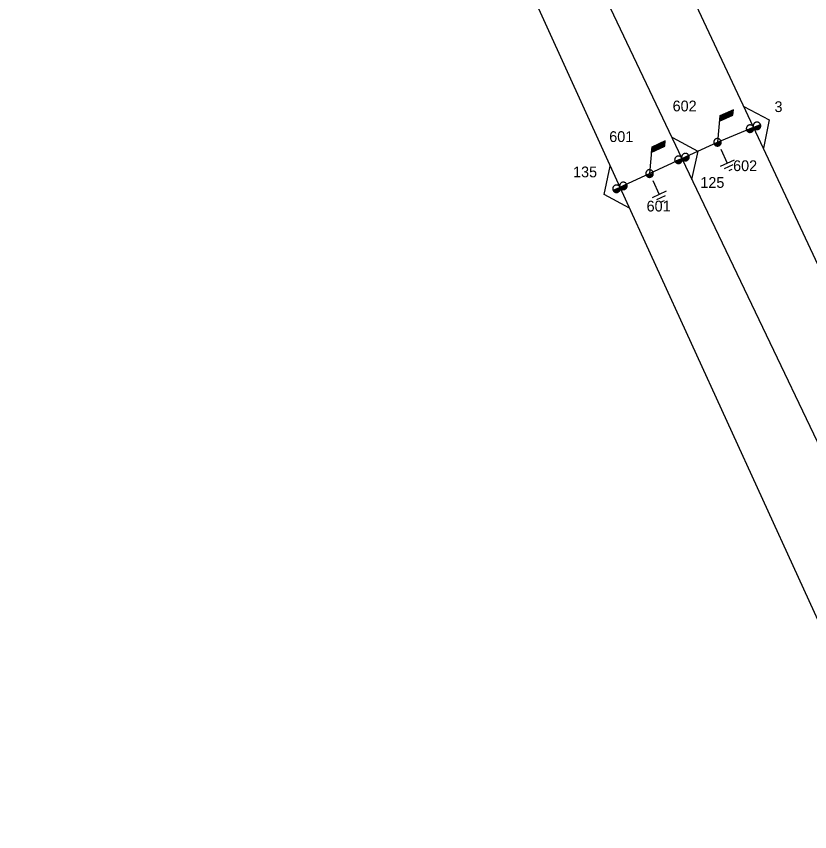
# Model space of a CAD drawing. Extents: x -536397 to -535454, y -1201642 to -1200953.
# Drawn here: x -536387.9 to -536258.8, y -1201274.9 to -1201142.3 of the extents above; entities that cross this region are included whole.
import ezdxf

# ---------------------------------------------------------------- set-up
doc = ezdxf.new("R2010")
doc.units = 0
for name, color, linetype in [('Default', 7, 'Continuous'), ('Vrstva 1', 7, 'Continuous'), ('Vrstva 11', 7, 'Continuous'), ('Vrstva 12', 7, 'Continuous'), ('Vrstva 13', 7, 'Continuous'), ('Vrstva 14', 7, 'Continuous'), ('Vrstva 15', 7, 'Continuous'), ('Vrstva 18', 7, 'Continuous'), ('Vrstva 2', 7, 'Continuous'), ('Vrstva 52', 7, 'Continuous')]:
    doc.layers.add(name, color=color, linetype=linetype)

# ---------------------------------------------------------------- blocks, each defined once
blk = doc.blocks.new('VN860')
at = {"layer": 'Vrstva 15'}
for points in [[(-3.74, 0), (0.01, 2.82)], [(0.01, 2.82), (3.76, 0)]]:
    blk.add_lwpolyline(points, dxfattribs=at)
blk = doc.blocks.new('VN440')
at = {"layer": 'Vrstva 2'}
for points in [[(1.22, 0), (1.21, 0.13), (1.19, 0.25), (1.16, 0.38), (1.11, 0.5), (1.05, 0.61), (0.98, 0.72), (0.9, 0.82), (0.81, 0.91), (0.71, 0.99), (0.6, 1.06), (0.49, 1.12), (0.37, 1.16), (0.25, 1.2), (0.12, 1.22), (-0.01, 1.22), (-0.14, 1.22), (-0.26, 1.2), (-0.39, 1.16), (-0.51, 1.12), (-0.62, 1.06), (-0.73, 0.99), (-0.83, 0.91), (-0.92, 0.82), (-1, 0.72), (-1.07, 0.61), (-1.13, 0.5), (-1.18, 0.38), (-1.21, 0.25), (-1.23, 0.13), (-1.24, 0), (-1.23, -0.13), (-1.21, -0.26), (-1.18, -0.38), (-1.13, -0.5), (-1.07, -0.62), (-1, -0.73), (-0.92, -0.83), (-0.83, -0.92), (-0.73, -1), (-0.62, -1.07), (-0.51, -1.13), (-0.39, -1.17), (-0.26, -1.2), (-0.14, -1.23), (-0.01, -1.23), (0.12, -1.23), (0.25, -1.2), (0.37, -1.17), (0.49, -1.13), (0.6, -1.07), (0.71, -1), (0.81, -0.92), (0.9, -0.83), (0.98, -0.73), (1.05, -0.62), (1.11, -0.5), (1.16, -0.38), (1.19, -0.26), (1.21, -0.13), (1.22, 0)], [(-1.24, 0), (1.22, 0)], [(-1.18, -0.34), (1.1, -0.34)], [(-1.01, -0.63), (0.97, -0.63)], [(-0.74, -0.92), (0.68, -0.92)]]:
    blk.add_lwpolyline(points, dxfattribs=at)
blk = doc.blocks.new('VN810')
at = {"layer": 'Vrstva 14'}
for points in [[(0, -1.25), (0, -3.75)], [(1.25, -3.75), (-1.25, -3.75)], [(0.77, -4.37), (-0.8, -4.37)], [(0, -5), (-0.25, -5)], [(0.27, -5), (0, -5)]]:
    blk.add_lwpolyline(points, dxfattribs=at)
blk = doc.blocks.new('VN450')
at = {"layer": 'Vrstva 2'}
for points in [[(0, 0), (-0.01, 0.13), (-0.03, 0.25), (-0.06, 0.38), (-0.11, 0.5), (-0.16, 0.61), (-0.23, 0.72), (-0.31, 0.82), (-0.4, 0.91), (-0.5, 0.99), (-0.61, 1.06), (-0.72, 1.11), (-0.84, 1.16), (-0.97, 1.19), (-1.09, 1.21), (-1.22, 1.22), (-1.35, 1.21), (-1.47, 1.19), (-1.59, 1.16), (-1.71, 1.11), (-1.83, 1.06), (-1.93, 0.99), (-2.03, 0.91), (-2.12, 0.82), (-2.2, 0.72), (-2.27, 0.61), (-2.33, 0.5), (-2.38, 0.38), (-2.41, 0.25), (-2.43, 0.13), (-2.44, 0), (-2.43, -0.13), (-2.41, -0.25), (-2.38, -0.38), (-2.33, -0.5), (-2.27, -0.61), (-2.2, -0.72), (-2.12, -0.82), (-2.03, -0.91), (-1.93, -0.99), (-1.83, -1.06), (-1.71, -1.11), (-1.59, -1.16), (-1.47, -1.19), (-1.35, -1.21), (-1.22, -1.22), (-1.09, -1.21), (-0.97, -1.19), (-0.84, -1.16), (-0.72, -1.11), (-0.61, -1.06), (-0.5, -0.99), (-0.4, -0.91), (-0.31, -0.82), (-0.23, -0.72), (-0.16, -0.61), (-0.11, -0.5), (-0.06, -0.38), (-0.03, -0.25), (-0.01, -0.13), (0, 0)], [(-2.44, 0), (2.44, 0)], [(2.44, 0), (2.43, 0.13), (2.41, 0.25), (2.38, 0.38), (2.33, 0.5), (2.27, 0.61), (2.2, 0.72), (2.12, 0.82), (2.03, 0.91), (1.94, 0.99), (1.83, 1.06), (1.71, 1.11), (1.6, 1.16), (1.47, 1.19), (1.35, 1.21), (1.22, 1.22), (1.09, 1.21), (0.97, 1.19), (0.84, 1.16), (0.72, 1.11), (0.61, 1.06), (0.5, 0.99), (0.4, 0.91), (0.31, 0.82), (0.23, 0.72), (0.16, 0.61), (0.11, 0.5), (0.06, 0.38), (0.03, 0.25), (0.01, 0.13), (0, 0), (0.01, -0.13), (0.03, -0.25), (0.06, -0.38), (0.11, -0.5), (0.16, -0.61), (0.23, -0.72), (0.31, -0.82), (0.4, -0.91), (0.5, -0.99), (0.61, -1.06), (0.72, -1.11), (0.84, -1.16), (0.97, -1.19), (1.09, -1.21), (1.22, -1.22), (1.35, -1.21), (1.47, -1.19), (1.6, -1.16), (1.71, -1.11), (1.83, -1.06), (1.94, -0.99), (2.03, -0.91), (2.12, -0.82), (2.2, -0.72), (2.27, -0.61), (2.33, -0.5), (2.38, -0.38), (2.41, -0.25), (2.43, -0.13), (2.44, 0)], [(-2.4, -0.31), (-0.04, -0.31)], [(-2.26, -0.61), (-0.17, -0.61)], [(-2.01, -0.92), (-0.42, -0.92)], [(0.04, -0.31), (2.4, -0.31)], [(0.17, -0.61), (2.27, -0.61)], [(0.42, -0.92), (2.02, -0.92)]]:
    blk.add_lwpolyline(points, dxfattribs=at)
blk = doc.blocks.new('VN001')
at = {"layer": 'Default'}
for p, q in [((1.73, 3.03), (4.14, 3.03)), ((1.76, 3.08), (4.17, 3.08)), ((1.79, 3.13), (4.2, 3.13)), ((1.82, 3.18), (4.23, 3.18)), ((1.85, 3.23), (4.26, 3.23)), ((1.87, 3.28), (4.29, 3.28)), ((1.9, 3.33), (4.32, 3.33)), ((1.93, 3.38), (4.35, 3.38)), ((1.96, 3.43), (4.37, 3.43)), ((1.99, 3.48), (4.4, 3.48)), ((2.02, 3.53), (4.43, 3.53)), ((2.05, 3.58), (4.46, 3.58)), ((2.07, 3.63), (4.49, 3.63)), ((2.1, 3.68), (4.52, 3.68)), ((2.13, 3.73), (2.54, 3.73))]:
    blk.add_line(p, q, dxfattribs=at)
blk.add_lwpolyline([(2.13, 3.73), (0, 0)], dxfattribs=at)
blk.add_lwpolyline([(4.55, 3.73), (2.13, 3.73), (1.7, 2.98), (4.12, 2.99)], close=True, dxfattribs=at)

msp = doc.modelspace()

# ---------------------------------------------------------------- linework, layer by layer
at = {"layer": 'Vrstva 1'}
for points in [[(-536387.85, -1200953.47), (-536384.37, -1200962.05), (-536350.06, -1201037.34), (-536318.97, -1201105.71), (-536289.66, -1201170.08)], [(-536346.44, -1200953.53), (-536361.66, -1200993.24), (-536320.28, -1201079.87), (-536279.58, -1201165.38)], [(-536267.93, -1201160.31), (-536301.44, -1201088.98), (-536346, -1200993.45), (-536331, -1200953.56)], [(-536219.16, -1201264.03), (-536230.39, -1201240.36), (-536267.93, -1201160.31)], [(-536279.58, -1201165.38), (-536243.88, -1201240.11), (-536226.82, -1201274.86)], [(-536289.66, -1201170.08), (-536254.89, -1201246.15), (-536245.11, -1201268.29)]]:
    msp.add_lwpolyline(points, dxfattribs=at)
at = {"layer": 'Vrstva 52'}
for points in [[(-536273.79, -1201162.75), (-536267.93, -1201160.31)], [(-536279.58, -1201165.38), (-536273.79, -1201162.75)], [(-536284.84, -1201167.84), (-536279.58, -1201165.38)], [(-536289.66, -1201170.08), (-536284.84, -1201167.84)]]:
    msp.add_lwpolyline(points, dxfattribs=at)

# ---------------------------------------------------------------- block references
at = {"layer": 'Vrstva 11'}
for p, rotation in [((-536273.79, -1201162.75), 24.430336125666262), ((-536284.84, -1201167.84), 24.930505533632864)]:
    msp.add_blockref('VN001', p, dxfattribs=dict(at, rotation=rotation))
at = {"layer": 'Vrstva 13'}
for name, p, xscale, yscale, rotation in [('VN450', (-536267.93, -1201160.31), 0.5, 0.49999999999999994, 22.062133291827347), ('VN440', (-536273.79, -1201162.75), 0.5, 0.5, 24.430336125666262), ('VN450', (-536279.58, -1201165.38), 0.5000000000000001, 0.5, 21.177100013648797), ('VN440', (-536284.84, -1201167.84), 0.5, 0.5, 24.930505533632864), ('VN450', (-536289.66, -1201170.08), 0.5, 0.5, 22.397825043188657)]:
    msp.add_blockref(name, p, dxfattribs=dict(at, xscale=xscale, yscale=yscale, rotation=rotation))
at = {"layer": 'Vrstva 15'}
for p, rotation in [((-536273.79, -1201162.75), 24.428316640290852), ((-536284.84, -1201167.84), 24.92261942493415)]:
    msp.add_blockref('VN810', p, dxfattribs=dict(at, rotation=rotation))
at = {"layer": 'Vrstva 18'}
for p, rotation in [((-536267.93, -1201160.31), -64.87544721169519), ((-536279.58, -1201165.38), -65.51085832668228), ((-536289.66, -1201170.08), 114.56414439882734)]:
    msp.add_blockref('VN860', p, dxfattribs=dict(at, rotation=rotation))

# ---------------------------------------------------------------- texts
at = {"layer": 'Vrstva 12'}
for s, p in [('602', (-536281.09, -1201157.73)), ('601', (-536291.4, -1201162.71))]:
    msp.add_text(s, height=1.75, dxfattribs=at).set_placement(p)
at = {"layer": 'Vrstva 14'}
for s, p in [('3', (-536264.52, -1201157.84)), ('602', (-536271.25, -1201167.44)), ('135', (-536297.28, -1201168.45)), ('125', (-536276.58, -1201170.17)), ('601', (-536285.32, -1201174.01))]:
    msp.add_text(s, height=1.75, dxfattribs=at).set_placement(p)

doc.saveas('drawing.dxf')
